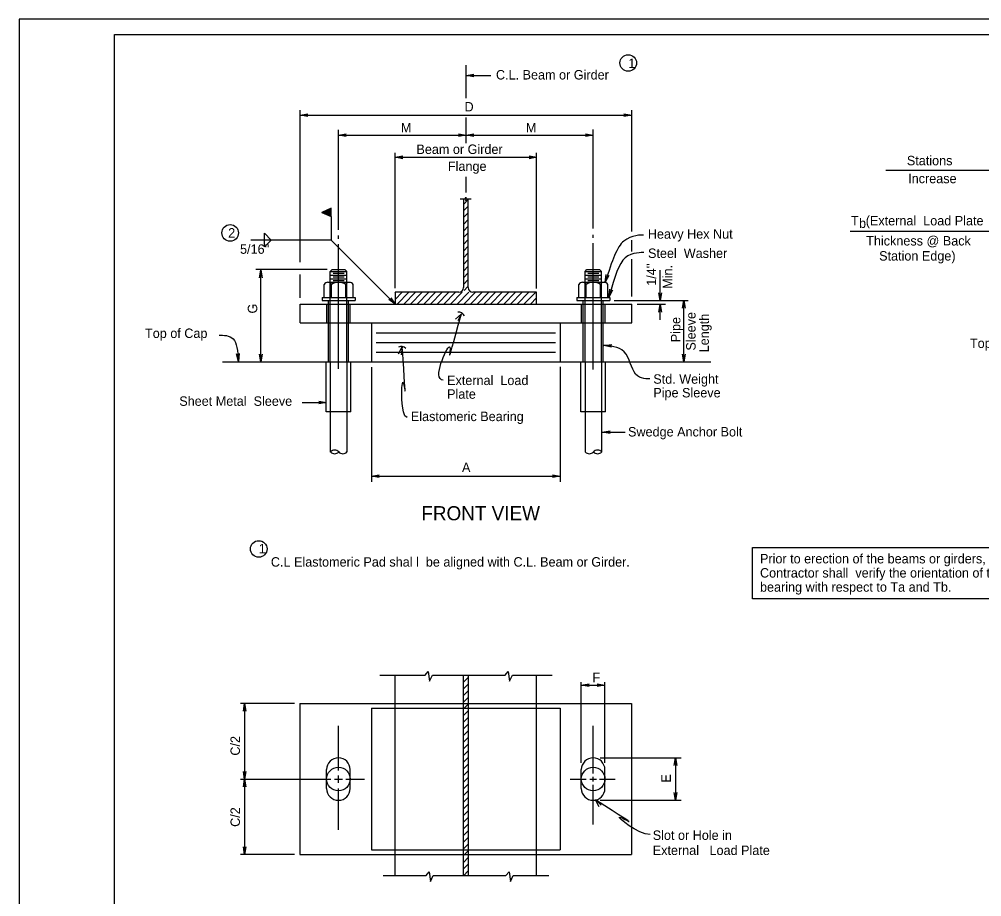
# Model space of a CAD drawing. Extents: x 32334 to 32601, y -901 to -733.
# Drawn here: x 32334.2 to 32436.3, y -826 to -733 of the extents above; entities that cross this region are included whole.
import ezdxf

# ---------------------------------------------------------------- set-up
doc = ezdxf.new("R2010")
doc.units = 0
for name, color, linetype in [('1', 7, 'Continuous'), ('B_Dimension', 7, 'Continuous'), ('Level 1', 7, 'Continuous'), ('Level 63', 7, 'Continuous')]:
    doc.layers.add(name, color=color, linetype=linetype)

msp = doc.modelspace()

# ---------------------------------------------------------------- linework, layer by layer
at = {"layer": '1'}
for p, q in [((32381.6, -741.38), (32381.6, -737.87)), ((32381.6, -738.97), (32384.21, -738.97)), ((32363.99, -758.76), (32363.99, -742.65)), ((32399.15, -755.49), (32399.15, -742.65)), ((32363.99, -743.19), (32399.15, -743.19)), ((32381.6, -746.15), (32381.6, -743.43)), ((32368.07, -755.33), (32368.07, -744.72)), ((32395.07, -755.2), (32395.07, -744.71)), ((32368.07, -745.31), (32381.6, -745.31)), ((32381.6, -745.31), (32395.07, -745.31)), ((32374.07, -761.51), (32374.07, -747.17)), ((32374.07, -747.64), (32389.09, -747.64)), ((32389.07, -761.54), (32389.07, -747.17)), ((32381.6, -751.38), (32381.6, -749.7)), ((32426.1, -749.02), (32438.8, -749.02)), ((32381.48, -752.04), (32381.57, -751.87)), ((32381.57, -751.87), (32381.57, -752.26)), ((32380.95, -752.04), (32381.48, -752.04)), ((32381.32, -752.04), (32381.32, -761.45)), ((32381.57, -752.26), (32381.64, -752.04)), ((32381.64, -752.04), (32382.13, -752.04)), ((32381.82, -761.45), (32381.82, -752.04)), ((32367.29, -753.02), (32366.31, -753.48)), ((32366.31, -753.48), (32367.29, -753.93)), ((32367.29, -753.93), (32367.29, -753.02)), ((32367.29, -753.02), (32367.29, -753.02)), ((32367.29, -753.93), (32367.29, -754.3)), ((32367.29, -754.3), (32367.29, -756.41)), ((32360.21, -757.12), (32360.21, -755.7)), ((32360.21, -755.7), (32360.92, -756.41)), ((32368.07, -756.27), (32368.07, -755.94)), ((32395.07, -756.19), (32395.07, -755.86)), ((32422.32, -755.47), (32439.1, -755.47)), ((32367.29, -756.41), (32358.78, -756.41)), ((32360.92, -756.41), (32360.21, -757.12)), ((32374.07, -763.2), (32367.29, -756.41)), ((32368.07, -770.06), (32368.07, -756.84)), ((32395.07, -770.12), (32395.07, -756.75)), ((32399.15, -757.63), (32399.15, -756.43)), ((32399.15, -762.39), (32399.15, -758.45)), ((32366.87, -759.53), (32359.29, -759.53)), ((32359.84, -769.32), (32359.84, -759.58)), ((32363.99, -762.53), (32363.99, -760.06)), ((32367.39, -759.53), (32367.2, -759.73)), ((32367.2, -760.89), (32367.2, -759.73)), ((32367.2, -759.73), (32368.95, -759.73)), ((32367.2, -760.12), (32368.95, -760.12)), ((32367.39, -759.53), (32368.75, -759.53)), ((32367.49, -759.92), (32368.66, -759.92)), ((32368.75, -759.53), (32368.95, -759.73)), ((32368.95, -760.89), (32368.95, -759.73)), ((32394.2, -759.73), (32394.39, -759.53)), ((32394.2, -759.73), (32395.95, -759.73)), ((32394.2, -760.89), (32394.2, -759.73)), ((32394.2, -759.73), (32395.95, -759.73)), ((32394.2, -760.12), (32395.95, -760.12)), ((32394.39, -759.53), (32395.75, -759.53)), ((32394.49, -759.92), (32395.66, -759.92)), ((32395.75, -759.53), (32395.95, -759.73)), ((32395.95, -760.89), (32395.95, -759.73)), ((32402.17, -762.83), (32402.17, -759.6)), ((32366.55, -762.5), (32366.55, -761.11)), ((32366.93, -760.89), (32369.22, -760.89)), ((32367.2, -760.51), (32368.95, -760.51)), ((32367.2, -769.32), (32367.2, -760.89)), ((32367.32, -762.5), (32367.32, -761.11)), ((32367.49, -760.31), (32368.66, -760.31)), ((32367.49, -760.7), (32368.66, -760.7)), ((32368.83, -762.5), (32368.83, -761.11)), ((32368.95, -769.32), (32368.95, -760.89)), ((32369.61, -762.5), (32369.61, -761.11)), ((32393.55, -762.5), (32393.55, -761.11)), ((32393.93, -760.89), (32396.22, -760.89)), ((32394.2, -760.51), (32395.95, -760.51)), ((32394.2, -769.32), (32394.2, -760.89)), ((32394.32, -762.5), (32394.32, -761.11)), ((32394.49, -760.31), (32395.66, -760.31)), ((32394.49, -760.7), (32395.66, -760.7)), ((32395.83, -762.5), (32395.83, -761.11)), ((32395.95, -769.32), (32395.95, -760.89)), ((32396.61, -762.5), (32396.61, -761.11)), ((32380.82, -761.95), (32374.07, -761.95)), ((32374.07, -761.95), (32374.07, -763.2)), ((32389.07, -761.95), (32382.32, -761.95)), ((32389.07, -763.2), (32389.07, -761.95)), ((32363.99, -765.2), (32363.99, -763.2)), ((32363.99, -763.2), (32399.15, -763.2)), ((32366.32, -762.5), (32369.82, -762.5)), ((32366.32, -762.5), (32366.32, -762.81)), ((32366.32, -762.81), (32369.82, -762.81)), ((32366.82, -765.2), (32366.82, -763.21)), ((32367.01, -763.21), (32367.01, -762.82)), ((32367.01, -765.2), (32367.01, -763.21)), ((32369.14, -763.21), (32369.14, -762.82)), ((32369.14, -765.2), (32369.14, -763.21)), ((32369.32, -765.2), (32369.32, -763.21)), ((32369.82, -762.5), (32369.82, -762.81)), ((32393.32, -762.5), (32396.82, -762.5)), ((32393.32, -762.5), (32393.32, -762.81)), ((32393.32, -762.81), (32396.82, -762.81)), ((32393.82, -765.21), (32393.82, -763.21)), ((32394.01, -763.21), (32394.01, -762.81)), ((32394.01, -765.21), (32394.01, -763.21)), ((32396.14, -763.21), (32396.14, -762.82)), ((32396.82, -762.5), (32396.82, -762.81)), ((32397.3, -762.81), (32405.12, -762.81)), ((32399.15, -765.2), (32399.15, -763.2)), ((32399.73, -763.2), (32402.72, -763.2)), ((32404.66, -769.32), (32404.66, -762.81)), ((32396.14, -765.22), (32396.14, -763.24)), ((32396.32, -765.22), (32396.32, -763.24)), ((32402.17, -764.88), (32402.17, -763.23)), ((32363.99, -765.2), (32399.15, -765.2)), ((32367.01, -769.32), (32367.01, -765.2)), ((32369.14, -769.32), (32369.14, -765.2)), ((32371.57, -765.2), (32371.57, -769.32)), ((32391.57, -765.2), (32391.57, -769.32)), ((32394.01, -769.32), (32394.01, -765.21)), ((32396.14, -769.32), (32396.14, -765.22)), ((32372.07, -766.23), (32391.07, -766.23)), ((32372.07, -767.26), (32391.07, -767.26)), ((32372.07, -768.29), (32391.07, -768.29)), ((32355.78, -769.32), (32407.54, -769.32)), ((32366.77, -774.61), (32366.77, -769.32)), ((32367.2, -769.32), (32367.2, -774.61)), ((32368.95, -769.32), (32368.95, -774.61)), ((32369.38, -774.61), (32369.38, -769.32)), ((32393.77, -774.61), (32393.77, -769.32)), ((32394.2, -769.32), (32394.2, -774.61)), ((32395.95, -769.32), (32395.95, -774.61)), ((32396.38, -774.61), (32396.38, -769.32)), ((32371.57, -769.89), (32371.57, -782.02)), ((32391.57, -769.84), (32391.57, -782.02)), ((32364.2, -773.64), (32366.79, -773.64)), ((32369.38, -774.61), (32366.77, -774.61)), ((32367.2, -774.61), (32367.2, -778.89)), ((32368.95, -774.61), (32368.95, -778.88)), ((32396.38, -774.61), (32393.77, -774.61)), ((32394.2, -774.61), (32394.2, -778.84)), ((32395.95, -774.61), (32395.95, -778.85)), ((32396.03, -776.76), (32398.46, -776.76)), ((32371.57, -781.45), (32391.57, -781.45)), ((32372.46, -802.52), (32377.25, -802.52)), ((32374.06, -823.75), (32374.06, -802.52)), ((32378.03, -802.52), (32385.72, -802.52)), ((32381.31, -823.75), (32381.31, -802.52)), ((32381.81, -802.52), (32381.81, -823.75)), ((32386.5, -802.52), (32390.71, -802.52)), ((32389.06, -823.75), (32389.06, -802.52)), ((32393.81, -811.83), (32393.81, -803.28)), ((32393.81, -803.59), (32396.31, -803.59)), ((32396.31, -811.83), (32396.31, -803.28)), ((32363.4, -805.53), (32357.67, -805.53)), ((32358.12, -805.53), (32358.12, -813.55)), ((32363.98, -805.53), (32363.98, -821.53)), ((32363.98, -805.53), (32374.03, -805.53)), ((32371.56, -806.03), (32371.56, -821.03)), ((32371.56, -806.03), (32391.56, -806.03)), ((32374.03, -805.53), (32389.09, -805.53)), ((32389.09, -805.53), (32399.14, -805.53)), ((32391.56, -806.03), (32391.56, -821.03)), ((32399.14, -805.53), (32399.14, -821.53)), ((32368.06, -812.62), (32368.06, -807.89)), ((32395.06, -812.96), (32395.06, -807.89)), ((32395.82, -811.28), (32404.39, -811.28)), ((32403.8, -811.28), (32403.8, -815.78)), ((32366.81, -814.53), (32366.81, -812.53)), ((32368.06, -813.93), (32368.06, -813.17)), ((32369.31, -814.53), (32369.31, -812.53)), ((32393.81, -814.53), (32393.81, -812.53)), ((32396.31, -814.53), (32396.31, -812.53)), ((32357.67, -813.53), (32367.25, -813.53)), ((32358.12, -813.55), (32358.12, -821.53)), ((32367.63, -813.53), (32368.48, -813.53)), ((32368.86, -813.53), (32369.31, -813.53)), ((32369.31, -813.53), (32370.83, -813.53)), ((32392.61, -813.53), (32394.34, -813.53)), ((32394.72, -813.53), (32395.43, -813.53)), ((32395.06, -813.79), (32395.06, -813.29)), ((32395.06, -818.34), (32395.06, -814.15)), ((32395.72, -813.53), (32396.31, -813.53)), ((32396.31, -813.53), (32397.39, -813.53)), ((32368.06, -818.93), (32368.06, -814.54)), ((32395.82, -815.78), (32404.39, -815.78)), ((32371.56, -821.03), (32391.56, -821.03)), ((32363.4, -821.53), (32357.67, -821.53)), ((32363.98, -821.53), (32374.03, -821.53)), ((32374.03, -821.53), (32389.04, -821.53)), ((32389.04, -821.53), (32399.14, -821.53)), ((32372.8, -823.75), (32377.35, -823.75)), ((32378.12, -823.75), (32385.82, -823.75)), ((32386.6, -823.75), (32390.37, -823.75))]:
    msp.add_line(p, q, dxfattribs=at)
for points in [[(32381.39, -752.56), (32381.76, -752.18)], [(32381.39, -753.26), (32381.76, -752.89)], [(32366.33, -753.48), (32366.33, -753.47)], [(32366.38, -753.51), (32366.38, -753.45)], [(32366.43, -753.53), (32366.43, -753.42)], [(32366.48, -753.55), (32366.48, -753.4)], [(32366.53, -753.58), (32366.53, -753.38)], [(32366.58, -753.6), (32366.58, -753.35)], [(32366.64, -753.63), (32366.64, -753.33)], [(32366.69, -753.65), (32366.69, -753.3)], [(32366.74, -753.67), (32366.74, -753.28)], [(32366.79, -753.7), (32366.79, -753.26)], [(32366.84, -753.72), (32366.84, -753.23)], [(32366.89, -753.75), (32366.89, -753.21)], [(32366.95, -753.77), (32366.95, -753.18)], [(32367, -753.79), (32367, -753.16)], [(32367.05, -753.82), (32367.05, -753.14)], [(32367.1, -753.84), (32367.1, -753.11)], [(32367.15, -753.87), (32367.15, -753.09)], [(32367.2, -753.89), (32367.2, -753.06)], [(32367.26, -753.91), (32367.26, -753.04)], [(32381.39, -753.97), (32381.76, -753.6)], [(32381.39, -754.68), (32381.76, -754.3)], [(32381.39, -755.39), (32381.76, -755.01)], [(32381.39, -756.09), (32381.76, -755.72)], [(32381.39, -756.8), (32381.76, -756.43)], [(32381.39, -757.51), (32381.76, -757.13)], [(32381.39, -758.21), (32381.76, -757.84)], [(32381.39, -758.92), (32381.76, -758.55)], [(32381.39, -759.63), (32381.76, -759.25)], [(32381.39, -760.33), (32381.76, -759.96)], [(32381.39, -761.04), (32381.76, -760.67)], [(32374.07, -762.7), (32374.82, -761.95)], [(32374.07, -761.99), (32374.12, -761.95)], [(32374.28, -763.2), (32375.53, -761.95)], [(32374.99, -763.2), (32376.24, -761.95)], [(32375.7, -763.2), (32376.95, -761.95)], [(32376.4, -763.2), (32377.65, -761.95)], [(32377.11, -763.2), (32378.36, -761.95)], [(32377.82, -763.2), (32379.07, -761.95)], [(32378.52, -763.2), (32379.77, -761.95)], [(32379.23, -763.2), (32380.48, -761.95)], [(32379.94, -763.2), (32381.19, -761.95)], [(32380.65, -763.2), (32381.9, -761.95)], [(32381.35, -763.2), (32382.6, -761.95)], [(32381.39, -761.75), (32381.76, -761.37)], [(32382.06, -763.2), (32383.31, -761.95)], [(32382.77, -763.2), (32384.02, -761.95)], [(32383.47, -763.2), (32384.72, -761.95)], [(32384.18, -763.2), (32385.43, -761.95)], [(32384.89, -763.2), (32386.14, -761.95)], [(32385.6, -763.2), (32386.84, -761.95)], [(32386.3, -763.2), (32387.55, -761.95)], [(32387.01, -763.2), (32388.26, -761.95)], [(32387.72, -763.2), (32388.97, -761.95)], [(32368.2, -763.2), (32368.2, -763.2)], [(32369.62, -763.2), (32369.62, -763.2)], [(32370.32, -763.2), (32370.32, -763.2)], [(32388.42, -763.2), (32389.07, -762.55)], [(32393.79, -763.2), (32393.79, -763.2)], [(32377.25, -802.52), (32377.58, -802.13), (32377.72, -803.17), (32378.03, -802.52)], [(32381.31, -803.26), (32381.81, -802.76)], [(32385.72, -802.52), (32386.05, -802.13), (32386.2, -803.17), (32386.5, -802.52)], [(32381.31, -803.97), (32381.81, -803.47)], [(32381.31, -804.68), (32381.81, -804.18)], [(32381.31, -805.39), (32381.81, -804.89)], [(32381.31, -806.09), (32381.81, -805.59)], [(32381.31, -806.8), (32381.81, -806.3)], [(32381.31, -807.51), (32381.81, -807.01)], [(32381.31, -808.21), (32381.81, -807.71)], [(32381.31, -808.92), (32381.81, -808.42)], [(32381.31, -809.63), (32381.81, -809.13)], [(32381.31, -810.33), (32381.81, -809.84)], [(32381.31, -811.04), (32381.81, -810.54)], [(32381.31, -811.75), (32381.81, -811.25)], [(32381.31, -812.46), (32381.81, -811.96)], [(32381.31, -813.16), (32381.81, -812.66)], [(32381.31, -813.87), (32381.81, -813.37)], [(32381.31, -814.58), (32381.81, -814.08)], [(32381.31, -815.28), (32381.81, -814.79)], [(32381.31, -815.99), (32381.81, -815.49)], [(32381.31, -816.7), (32381.81, -816.2)], [(32381.31, -817.41), (32381.81, -816.91)], [(32381.31, -818.11), (32381.81, -817.61)], [(32381.31, -818.82), (32381.81, -818.32)], [(32381.31, -819.53), (32381.81, -819.03)], [(32381.31, -820.23), (32381.81, -819.74)], [(32381.31, -820.94), (32381.81, -820.44)], [(32381.31, -821.65), (32381.81, -821.15)], [(32381.31, -822.36), (32381.81, -821.86)], [(32377.35, -823.75), (32377.68, -823.36), (32377.82, -824.4), (32378.12, -823.75)], [(32381.31, -823.06), (32381.81, -822.56)], [(32381.31, -823.77), (32381.81, -823.27)], [(32385.82, -823.75), (32386.15, -823.36), (32386.29, -824.4), (32386.6, -823.75)]]:
    msp.add_lwpolyline(points, dxfattribs=at)
msp.add_lwpolyline([(32411.97, -789.01), (32447.26, -789.01), (32447.26, -794.42), (32411.97, -794.42)], close=True, dxfattribs=at)
for centre, radius in [((32398.78, -737.65), 0.88), ((32356.58, -755.66), 0.88), ((32359.61, -789.15), 0.88), ((32368.06, -813.53), 1.25), ((32395.06, -813.53), 1.25)]:
    msp.add_circle(centre, radius, dxfattribs=at)
for centre, radius, start, end in [((32366.93, -761.34), 0.45, 30.8086, 149.1914), ((32368.08, -762.31), 1.42, 57.6898, 122.3102), ((32369.22, -761.35), 0.452, 30.9573, 149.0427), ((32393.93, -761.34), 0.45, 30.8086, 149.1914), ((32395.08, -762.31), 1.42, 57.6898, 122.3102), ((32396.22, -761.35), 0.452, 30.9573, 149.0427), ((32380.83, -761.45), 0.5, 270, 360), ((32382.32, -761.45), 0.5, 180, 270), ((32380.84, -764.66), 0.615, 21.6992, 99.9226), ((32374.72, -768.29), 0.615, 40.3962, 118.6196), ((32367.66, -779.28), 0.605, 43.7135, 136.2865), ((32367.66, -778.45), 0.605, 223.7135, 316.2865), ((32368.53, -778.45), 0.605, 223.7135, 316.2865), ((32394.66, -778.45), 0.605, 223.7135, 316.2865), ((32395.53, -779.28), 0.605, 43.7135, 136.2865), ((32395.53, -778.45), 0.605, 223.7135, 316.2865), ((32368.06, -812.53), 1.25, 0, 180), ((32395.06, -812.53), 1.25, 0, 180), ((32368.06, -814.53), 1.25, 180, 0), ((32395.06, -814.53), 1.25, 180, 0)]:
    msp.add_arc(centre, radius, start, end, dxfattribs=at)
for points in [[(32400.41, -755.89), (32400.21, -755.88), (32397.97, -755.85), (32397.12, -758.49), (32396.34, -760.89)], [(32400.45, -757.74), (32400.25, -757.73), (32398.13, -757.65), (32397.39, -760.16), (32396.74, -762.46)], [(32379.17, -771.25), (32377.95, -771.25), (32381.1, -764.22), (32379.17, -771.25), (32381.1, -764.22)], [(32355.42, -766.51), (32355.84, -766.48), (32357.21, -766.49), (32357.37, -768.12), (32357.47, -769.28)], [(32375.33, -775.23), (32374.63, -775.19), (32374.83, -767.74), (32375.33, -775.23), (32374.83, -767.74)], [(32401.07, -771.13), (32400.87, -771.14), (32399.22, -771.22), (32398.8, -767.7), (32396.75, -767.62), (32396.21, -767.59)], [(32401.09, -819.42), (32399.8, -819.38), (32395.3, -815.74), (32401.09, -819.42), (32395.3, -815.74)]]:
    msp.add_open_spline(points, degree=3, dxfattribs=at)
at = {"layer": 'B_Dimension'}
for points in [[(32382.42, -739.11), (32381.6, -738.97), (32382.42, -738.82)], [(32364.81, -743.33), (32363.99, -743.19), (32364.81, -743.04)], [(32398.33, -743.04), (32399.15, -743.19), (32398.33, -743.33)], [(32368.89, -745.45), (32368.07, -745.31), (32368.89, -745.16)], [(32380.78, -745.16), (32381.6, -745.31), (32380.78, -745.45)], [(32382.42, -745.45), (32381.6, -745.31), (32382.42, -745.16)], [(32394.25, -745.16), (32395.07, -745.31), (32394.25, -745.45)], [(32374.89, -747.79), (32374.07, -747.64), (32374.89, -747.5)], [(32388.27, -747.5), (32389.09, -747.64), (32388.27, -747.79)], [(32359.7, -760.4), (32359.84, -759.58), (32359.99, -760.4)], [(32396.73, -760.16), (32396.34, -760.89), (32396.46, -760.07)], [(32397.1, -761.71), (32396.74, -762.46), (32396.83, -761.63)], [(32402.31, -762.01), (32402.17, -762.83), (32402.03, -762.01)], [(32373.6, -762.52), (32374.07, -763.2), (32373.39, -762.72)], [(32404.52, -763.63), (32404.66, -762.81), (32404.81, -763.63)], [(32380.48, -764.78), (32381.1, -764.22), (32380.71, -764.96)], [(32402.03, -764.05), (32402.17, -763.23), (32402.31, -764.05)], [(32374.42, -768.47), (32374.83, -767.74), (32374.7, -768.56)], [(32397.02, -767.77), (32396.21, -767.59), (32397.03, -767.48)], [(32357.54, -768.45), (32357.47, -769.28), (32357.25, -768.48)], [(32359.99, -768.5), (32359.84, -769.32), (32359.7, -768.5)], [(32404.81, -768.5), (32404.66, -769.32), (32404.52, -768.5)], [(32365.97, -773.49), (32366.79, -773.64), (32365.97, -773.78)], [(32396.85, -776.91), (32396.03, -776.76), (32396.85, -776.62)], [(32372.39, -781.59), (32371.57, -781.45), (32372.39, -781.3)], [(32390.75, -781.3), (32391.57, -781.45), (32390.75, -781.59)], [(32394.63, -803.74), (32393.81, -803.59), (32394.63, -803.45)], [(32395.49, -803.45), (32396.31, -803.59), (32395.49, -803.74)], [(32357.98, -806.35), (32358.12, -805.53), (32358.26, -806.35)], [(32403.66, -812.1), (32403.8, -811.28), (32403.95, -812.1)], [(32358.26, -812.73), (32358.12, -813.55), (32357.98, -812.73)], [(32357.98, -814.37), (32358.12, -813.55), (32358.26, -814.37)], [(32403.95, -814.96), (32403.8, -815.78), (32403.66, -814.96)], [(32395.69, -816.47), (32395.3, -815.74), (32395.92, -816.29)], [(32358.26, -820.71), (32358.12, -821.53), (32357.98, -820.71)]]:
    msp.add_lwpolyline(points, dxfattribs=at)
at = {"layer": 'Level 1'}
for p, q in [((32344.32, -734.63), (32597.26, -734.63)), ((32344.32, -899), (32344.32, -734.63))]:
    msp.add_line(p, q, dxfattribs=at)
at = {"layer": 'Level 63'}
msp.add_lwpolyline([(32334.22, -900.59), (32600.86, -900.59), (32600.86, -733.02), (32334.22, -733.02)], close=True, dxfattribs=at)

# ---------------------------------------------------------------- texts
at = {"layer": '1'}
for s, height, p in [('1', 1, (32398.79, -738.18)), ('C.L. Beam or Girder', 1, (32384.76, -739.4)), ('D', 1, (32381.43, -742.79)), ('M', 1, (32374.68, -745.01)), ('M', 1, (32387.93, -745.01)), ('Beam or Girder', 1, (32376.33, -747.29)), ('Stations', 1, (32428.32, -748.49)), ('Flange', 1, (32379.67, -749.09)), ('Increase', 1, (32428.46, -750.39)), ('T  (External  Load Plate', 1, (32422.4, -754.86)), ('b', 1, (32423.25, -755.13)), ('2', 1, (32356.37, -756.15)), ('Heavy Hex Nut', 1, (32400.86, -756.27)), ('Thickness @ Back', 1, (32424.01, -756.99)), ("5/16''", 1, (32357.63, -757.87)), ('Steel  Washer', 1, (32400.88, -758.31)), ('Station Edge)', 1, (32425.38, -758.59)), ('Top of Cap', 1, (32347.56, -766.79)), ('Top of Cap', 1, (32435.01, -767.85)), ('External  Load ', 1, (32379.58, -771.78)), ('Std. Weight ', 1, (32401.44, -771.64)), ('Plate', 1, (32379.58, -773.23)), ('Pipe Sleeve', 1, (32401.44, -773.09)), ('Sheet Metal  Sleeve', 1, (32351.19, -773.98)), ('Elastomeric Bearing', 1, (32375.74, -775.6)), ('Swedge Anchor Bolt', 1, (32398.76, -777.23)), ('A', 1, (32381.16, -781)), ('FRONT VIEW', 1.498, (32376.85, -786.11)), ('1', 1, (32359.62, -789.61)), ('Prior to erection of the beams or girders, the ', 1, (32412.75, -790.68)), ('C.L Elastomeric Pad shal l  be aligned with C.L. Beam or Girder.', 1, (32360.9, -791.02)), ('Contractor shall  verify the orientation of the ', 1, (32412.75, -792.18)), ('bearing with respect to Ta and Tb.', 1, (32412.75, -793.68)), ('F', 1, (32394.99, -803.27)), ('Slot or Hole in', 1, (32401.38, -819.98)), ('External   Load Plate', 1, (32401.38, -821.58))]:
    msp.add_text(s, height=height, dxfattribs=at).set_placement(p)
for s, p in [("1/4''", (32401.74, -761.26)), ('Min.', (32403.45, -761.58)), ('G', (32359.45, -764.2)), ('Sleeve ', (32405.92, -768.13)), ('Pipe', (32404.31, -767.24)), ('Length', (32407.33, -768.31)), ('C/2', (32357.62, -811.05)), ('E', (32403.3, -813.91)), ('C/2', (32357.62, -818.6))]:
    msp.add_text(s, height=1, rotation=90, dxfattribs=at).set_placement(p)

doc.saveas('drawing.dxf')
